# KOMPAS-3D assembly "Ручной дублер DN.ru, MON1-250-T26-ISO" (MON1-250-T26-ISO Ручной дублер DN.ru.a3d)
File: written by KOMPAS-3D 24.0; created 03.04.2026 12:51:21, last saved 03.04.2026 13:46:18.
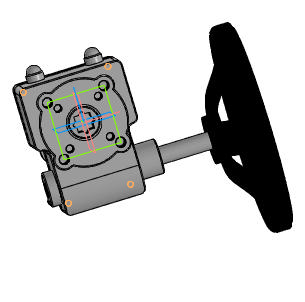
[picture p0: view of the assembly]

Document properties: Автор: R2D2; Полное имя файла: E:\Работа\Зайцев\Аксессуары для пневмоприводов\Ручной дублер DN.ru\MON1-250-T26-ISO Ручной дублер DN.ru\исходные материалы\MON1-250-T26-ISO Ручной дублер DN.ru.a3d

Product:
- Component [detail]: Деталь1  | qty 1  | pos. 1  | Масса: 5.630796; Автор: R2D2; additional columns: Типовые; source file: 3.m3d
- Component [detail]: Деталь1  | qty 1  | pos. 1  | Масса: 5.630796; Автор: R2D2; additional columns: Типовые; source file: 2.m3d
- Component [detail]: Деталь1  | qty 1  | pos. 1  | Масса: 5.630796; Автор: R2D2; additional columns: Типовые; source file: 1.m3d
- Component [detail]: Деталь 2  | qty 1  | pos. 2  | Масса: 1.734021; Автор: R2D2; additional columns: Типовые; source file: Деталь 2 Деталь 2.m3d
- Component [standard]: Hexagon socket head cap screw ISO 4762 - М6 x 10  | qty 4  | Материал: Не определено (density 0 kg/m3); Масса: 0.0047; Раздел спецификации: Стандартные изделия; Рассекать на разрезах: no
- Part/product: Ручной дублер DN.ru  | designation MON1-250-T26-ISO
    Масса: 3
    Раздел спецификации: Прочие изделия
    Примечание: D290-00336

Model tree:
1. Эскиз:2  (with: Грань.Операция без истории:1, Ребро.Операция без истории:1)
2. Элемент выдавливания:3
     Расстояние 2 = 10
3. Эскиз:3  (with: Грань.Операция без истории:1, Ребро.Операция без истории:1)
4. Элемент выдавливания:4  (with: Грань.Операция без истории:1, Грань.Элемент выдавливания:4)  (labels: Грань.Твердое тело1)
     Расстояние 2 = 13; Расстояние = -10; Расстояние = -120; Расстояние = -145

Referenced files in E:\Работа\Зайцев\Аксессуары для пневмоприводов\Ручной дублер DN.ru\MON1-250-T26-ISO Ручной дублер DN.ru\исходные материалы\: 3.m3d, 2.m3d, 1.m3d, Деталь 2 Деталь 2.m3d
Referenced files in C:\Program Files\ASCON\KOMPAS-3D v24\Libs\PolynomLib\DATA\vault\Methods\Kompas\3D\: PLib_Screw_DIN_7984_1500.m3d
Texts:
  Hexagon socket head cap screw
  BOSimple***PART:86906dfe-320b-4a65-fedb-73bd2ba9e651***SHORTLOC:A259_235BDFABBEFC4171[1;10;6;-;Undefined]
  Программные изделия  и базы данных
  MON1-250-T26-ISO
  Деталь1 Деталь1
  Деталь 2 Деталь 2
  Hexagon socket head cap screw ISO 4762 - М6 x 10 (1)
  Hexagon socket head cap screw ISO 4762 - М6 x 10 (2)
  Hexagon socket head cap screw ISO 4762 - М6 x 10 (4)
  Hexagon socket head cap screw ISO 4762 - М6 x 10 (6)
  Плоскость ZX.Начало координат
  Ось Y.Начало координат
  Плоскость XY.Начало координат
  Плоскость ZY.Начало координат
